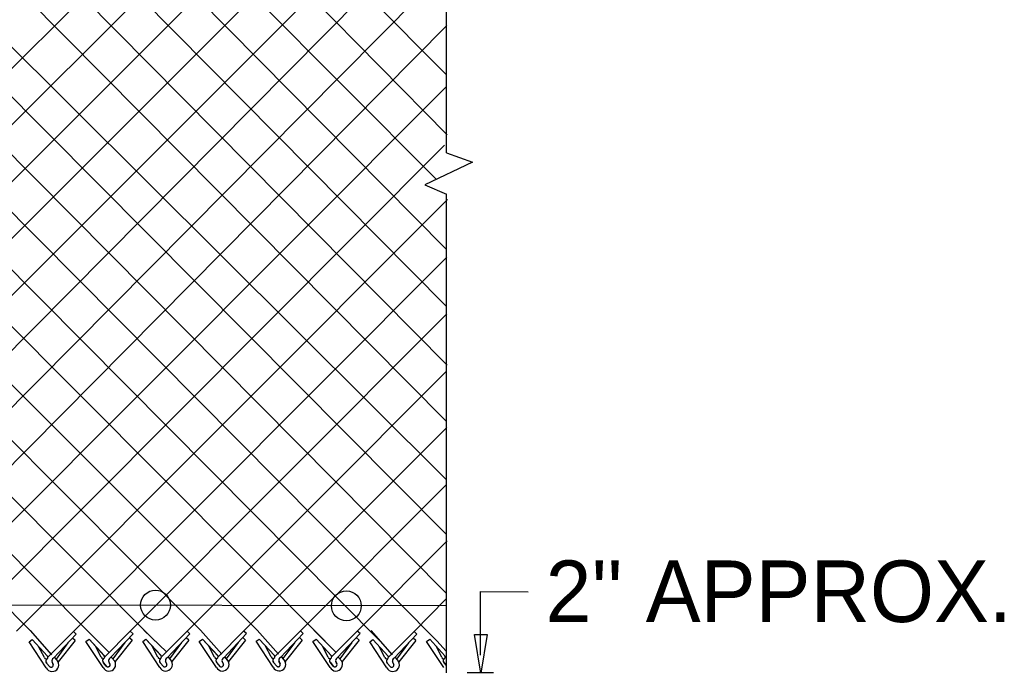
# Model space of a CAD drawing. Extents: x 0 to 2.85, y -0.1 to 1.83.
# Drawn here: x 1.173 to 1.3329, y 0.432 to 0.5382 of the extents above; entities that cross this region are included whole.
import ezdxf

# ---------------------------------------------------------------- set-up
doc = ezdxf.new("R2010")
doc.units = 0
for name, color, linetype in [('CT_Dimensions', 7, 'Continuous'), ('sb_Chainlink Fence', 7, 'Continuous'), ('sb_Existing Structural Steel', 7, 'Continuous')]:
    doc.layers.add(name, color=color, linetype=linetype)

msp = doc.modelspace()

# ---------------------------------------------------------------- linework, layer by layer
at = {"layer": 'CT_Dimensions'}
for p, q in [((1.2478234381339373, 0.4349259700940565), (1.2478234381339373, 0.4452738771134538)), ((1.2478234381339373, 0.4452738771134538), (1.2555261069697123, 0.44522173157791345)), ((1.245626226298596, 0.4321089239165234), (1.2499291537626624, 0.4321089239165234))]:
    msp.add_line(p, q, dxfattribs=at)
msp.add_lwpolyline([(1.248904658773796, 0.4382930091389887), (1.2478558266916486, 0.4320000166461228), (1.246806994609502, 0.4382930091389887)], close=True, dxfattribs=at)
at = {"layer": 'sb_Chainlink Fence'}
for p, q in [((1.2422905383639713, 0.5165766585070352), (1.2423058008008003, 0.5742715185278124)), ((1.1399018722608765, 0.5653949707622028), (1.242205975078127, 0.46352117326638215)), ((1.1170663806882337, 0.4387057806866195), (1.2423146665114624, 0.5641446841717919)), ((1.0856296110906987, 0.4444539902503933), (1.2030117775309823, 0.5615672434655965)), ((1.0889412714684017, 0.43860628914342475), (1.212232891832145, 0.5616340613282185)), ((1.098624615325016, 0.4387014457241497), (1.2214630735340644, 0.5617501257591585)), ((1.099199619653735, 0.5612496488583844), (1.2225566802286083, 0.4372006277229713)), ((1.1078450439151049, 0.4387247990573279), (1.2306873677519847, 0.5617466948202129)), ((1.1084207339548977, 0.5613164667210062), (1.231717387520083, 0.43698579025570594)), ((1.117650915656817, 0.5614325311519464), (1.2409415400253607, 0.43703703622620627)), ((1.1268752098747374, 0.5614291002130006), (1.242247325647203, 0.44502808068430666)), ((1.136094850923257, 0.5614703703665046), (1.2422290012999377, 0.45464034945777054)), ((1.1545640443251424, 0.561488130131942), (1.242202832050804, 0.4729775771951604)), ((1.1637851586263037, 0.5615549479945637), (1.2423944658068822, 0.4820903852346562)), ((1.1730153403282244, 0.5616710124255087), (1.2421925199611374, 0.49170328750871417)), ((1.1822396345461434, 0.5616675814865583), (1.2421467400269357, 0.5009699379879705)), ((1.1914592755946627, 0.5617088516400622), (1.2405411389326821, 0.5123525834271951)), ((1.200824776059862, 0.5617246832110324), (1.2424112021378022, 0.5194915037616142)), ((1.2100452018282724, 0.5617491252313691), (1.2422192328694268, 0.5293245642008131)), ((1.0895020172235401, 0.5610705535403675), (1.211527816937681, 0.43902946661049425)), ((1.0860534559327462, 0.5558884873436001), (1.20230738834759, 0.43900611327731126)), ((1.1262970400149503, 0.4386375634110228), (1.2423211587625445, 0.5558689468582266)), ((1.0860241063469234, 0.5466251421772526), (1.1949525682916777, 0.43724268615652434)), ((1.135521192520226, 0.4386888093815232), (1.242193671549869, 0.5464454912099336)), ((1.0853121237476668, 0.5380208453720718), (1.1838951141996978, 0.43899347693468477)), ((1.144345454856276, 0.4382857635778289), (1.2423139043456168, 0.5372986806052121)), ((1.0857454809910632, 0.5282548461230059), (1.1746709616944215, 0.43894223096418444)), ((1.154032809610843, 0.4388606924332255), (1.2422356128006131, 0.5273176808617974)), ((1.1632532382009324, 0.4388840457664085), (1.2419733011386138, 0.5178120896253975)), ((1.2422905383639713, 0.5165766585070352), (1.2465113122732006, 0.515088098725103)), ((1.2465113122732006, 0.515088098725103), (1.2387711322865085, 0.5114119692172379)), ((1.2387711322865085, 0.5114119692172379), (1.242288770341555, 0.509893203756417)), ((1.17247457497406, 0.4388650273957), (1.2424292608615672, 0.5090285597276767)), ((1.2422681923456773, 0.43210453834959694), (1.242288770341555, 0.509893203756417)), ((1.1817052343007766, 0.4387968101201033), (1.2423555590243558, 0.4996556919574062)), ((1.1909293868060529, 0.438848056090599), (1.2423543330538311, 0.49043740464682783)), ((1.2001491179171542, 0.43885457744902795), (1.242157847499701, 0.48101512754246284)), ((1.2093416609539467, 0.4388606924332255), (1.242357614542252, 0.4719717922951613)), ((1.218562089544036, 0.4388840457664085), (1.242224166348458, 0.4626086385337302)), ((1.2277834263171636, 0.4388650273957), (1.2424068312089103, 0.45351950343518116)), ((1.199139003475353, 0.44703465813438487), (1.1992236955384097, 0.4471193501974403)), ((1.0856561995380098, 0.44326039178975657), (1.2423033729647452, 0.4430188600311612)), ((1.1746709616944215, 0.43894223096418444), (1.1781461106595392, 0.43502934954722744)), ((1.1775522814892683, 0.43462621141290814), (1.1817052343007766, 0.4387968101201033)), ((1.178465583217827, 0.4344630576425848), (1.1821583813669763, 0.43838618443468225)), ((1.1821583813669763, 0.43838618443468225), (1.1817052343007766, 0.4387968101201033)), ((1.1838951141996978, 0.43899347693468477), (1.1874928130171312, 0.43540281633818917)), ((1.1867764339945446, 0.43467745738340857), (1.1909293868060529, 0.438848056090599)), ((1.1876897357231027, 0.4345143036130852), (1.1913825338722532, 0.43843743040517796)), ((1.1913825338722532, 0.43843743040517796), (1.1909293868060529, 0.438848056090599)), ((1.1931148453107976, 0.438999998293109), (1.196790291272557, 0.43548537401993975)), ((1.1959961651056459, 0.4346839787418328), (1.2001491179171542, 0.43885457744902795)), ((1.1969094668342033, 0.43452082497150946), (1.2006022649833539, 0.43844395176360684)), ((1.2006022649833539, 0.43844395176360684), (1.2001491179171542, 0.43885457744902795)), ((1.20230738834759, 0.43900611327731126), (1.2057825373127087, 0.4350932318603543)), ((1.2051887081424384, 0.4346900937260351), (1.2093416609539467, 0.4388606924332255)), ((1.2061020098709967, 0.4345269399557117), (1.2097948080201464, 0.43845006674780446)), ((1.2097948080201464, 0.43845006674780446), (1.2093416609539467, 0.4388606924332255)), ((1.211527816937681, 0.43902946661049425), (1.2150029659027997, 0.43511658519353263)), ((1.2144091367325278, 0.43471344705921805), (1.218562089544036, 0.4388840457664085)), ((1.2153224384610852, 0.43455029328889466), (1.2190152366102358, 0.43847342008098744)), ((1.2190152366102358, 0.43847342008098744), (1.218562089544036, 0.4388840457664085)), ((1.2207491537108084, 0.43901044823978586), (1.2243642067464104, 0.43539080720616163)), ((1.2236304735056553, 0.4346944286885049), (1.2277834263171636, 0.4388650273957)), ((1.224543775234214, 0.43453127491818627), (1.228236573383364, 0.438454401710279)), ((1.228236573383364, 0.438454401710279), (1.2277834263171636, 0.4388650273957)), ((1.2299798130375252, 0.43894223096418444), (1.2334549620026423, 0.43502934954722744)), ((1.232861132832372, 0.43462621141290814), (1.2370140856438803, 0.4387968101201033)), ((1.233774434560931, 0.4344630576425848), (1.23746723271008, 0.43838618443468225)), ((1.23746723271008, 0.43838618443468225), (1.2370140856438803, 0.4387968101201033)), ((1.1745060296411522, 0.43712460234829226), (1.175016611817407, 0.4374734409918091)), ((1.1772955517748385, 0.4329011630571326), (1.1745060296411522, 0.43712460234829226)), ((1.175016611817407, 0.4374734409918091), (1.1774850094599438, 0.43481311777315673)), ((1.175016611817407, 0.4374734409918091), (1.1775008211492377, 0.4347973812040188)), ((1.1808150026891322, 0.43694584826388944), (1.178872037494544, 0.43430117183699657)), ((1.1820045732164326, 0.4373260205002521), (1.1792421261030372, 0.4338515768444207)), ((1.1820045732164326, 0.4373260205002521), (1.181551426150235, 0.43773664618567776)), ((1.1837301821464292, 0.4371758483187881), (1.1842407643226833, 0.43752468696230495)), ((1.1865197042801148, 0.4329524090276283), (1.1837301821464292, 0.4371758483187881)), ((1.1842407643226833, 0.43752468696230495), (1.1867091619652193, 0.4348643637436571)), ((1.1842407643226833, 0.43752468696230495), (1.186724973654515, 0.4348486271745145)), ((1.1900391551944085, 0.43699709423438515), (1.1880961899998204, 0.43435241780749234)), ((1.191228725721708, 0.4373772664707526), (1.1884662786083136, 0.4339028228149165)), ((1.191228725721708, 0.4373772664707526), (1.1907755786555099, 0.4377878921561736)), ((1.1929499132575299, 0.4371823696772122), (1.1934604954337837, 0.43753120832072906)), ((1.195739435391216, 0.4329589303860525), (1.1929499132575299, 0.4371823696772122)), ((1.1934604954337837, 0.43753120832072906), (1.1959288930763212, 0.4348708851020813)), ((1.1934604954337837, 0.43753120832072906), (1.1959447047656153, 0.4348551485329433)), ((1.1992588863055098, 0.4370036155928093), (1.1973159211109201, 0.43435893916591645)), ((1.2004484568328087, 0.43738378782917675), (1.1976860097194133, 0.43390934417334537)), ((1.2004484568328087, 0.43738378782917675), (1.1999953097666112, 0.4377944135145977)), ((1.2021424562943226, 0.43718848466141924), (1.2026530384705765, 0.43753732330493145)), ((1.204931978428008, 0.4329650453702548), (1.2021424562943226, 0.43718848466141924)), ((1.2026530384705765, 0.43753732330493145), (1.205121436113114, 0.43487700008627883)), ((1.2026530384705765, 0.43753732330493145), (1.205137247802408, 0.4348612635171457)), ((1.2084514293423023, 0.43700973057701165), (1.2065084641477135, 0.43436505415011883)), ((1.2096409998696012, 0.4373899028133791), (1.2068785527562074, 0.433915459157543)), ((1.2096409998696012, 0.4373899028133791), (1.2091878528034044, 0.4378005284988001)), ((1.211362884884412, 0.43721183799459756), (1.2118734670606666, 0.43756067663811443)), ((1.214152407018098, 0.4329883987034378), (1.211362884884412, 0.43721183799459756)), ((1.2118734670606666, 0.43756067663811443), (1.2143418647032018, 0.4349003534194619)), ((1.2118734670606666, 0.43756067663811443), (1.2143576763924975, 0.4348846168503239)), ((1.2176718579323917, 0.4370330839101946), (1.2157288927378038, 0.4343884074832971)), ((1.2188614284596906, 0.437413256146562), (1.2160989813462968, 0.43393881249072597)), ((1.2188614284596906, 0.437413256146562), (1.218408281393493, 0.43782388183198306)), ((1.2205842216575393, 0.437192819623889), (1.2210948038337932, 0.4375416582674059)), ((1.2233737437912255, 0.4329693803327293), (1.2205842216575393, 0.437192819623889)), ((1.2210948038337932, 0.4375416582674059), (1.2235632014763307, 0.4348813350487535)), ((1.2210948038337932, 0.4375416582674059), (1.2235790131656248, 0.4348655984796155)), ((1.2268931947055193, 0.43701406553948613), (1.2249502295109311, 0.43436938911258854)), ((1.2280827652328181, 0.43739423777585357), (1.2253203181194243, 0.4339197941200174)), ((1.2280827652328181, 0.43739423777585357), (1.227629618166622, 0.4378048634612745)), ((1.229814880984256, 0.43712460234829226), (1.2303254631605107, 0.4374734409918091)), ((1.2326044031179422, 0.4329011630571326), (1.229814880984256, 0.43712460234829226)), ((1.2303254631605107, 0.4374734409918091), (1.2327938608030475, 0.43481311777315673)), ((1.2303254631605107, 0.4374734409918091), (1.2328096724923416, 0.4347973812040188)), ((1.236123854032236, 0.43694584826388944), (1.2341808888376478, 0.43430117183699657)), ((1.2373134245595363, 0.4373260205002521), (1.234550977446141, 0.4338515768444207)), ((1.2373134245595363, 0.4373260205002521), (1.236860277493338, 0.43773664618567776)), ((1.2390390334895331, 0.4371758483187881), (1.239549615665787, 0.43752468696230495)), ((1.2418285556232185, 0.4329524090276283), (1.2390390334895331, 0.4371758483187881)), ((1.239549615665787, 0.43752468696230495), (1.242018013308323, 0.4348643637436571)), ((1.239549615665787, 0.43752468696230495), (1.2420338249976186, 0.4348486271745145)), ((1.2407177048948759, 0.43728906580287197), (1.24223882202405, 0.4355763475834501)), ((1.1769779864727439, 0.43456755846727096), (1.1760487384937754, 0.4363439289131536)), ((1.1862021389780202, 0.43461880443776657), (1.1852728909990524, 0.4363951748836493)), ((1.19542187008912, 0.4346253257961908), (1.1944926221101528, 0.43640169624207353)), ((1.204614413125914, 0.4346314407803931), (1.2036851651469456, 0.4364078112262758)), ((1.2138348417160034, 0.43465479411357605), (1.212905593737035, 0.4364311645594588)), ((1.223056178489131, 0.4346357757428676), (1.2221269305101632, 0.43641214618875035)), ((1.2322868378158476, 0.43456755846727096), (1.2313575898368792, 0.4363439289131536)), ((1.2415109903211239, 0.43461880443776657), (1.2405817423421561, 0.4363951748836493)), ((1.1778126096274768, 0.4331129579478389), (1.177350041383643, 0.43366683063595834)), ((1.177350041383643, 0.43366683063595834), (1.17785966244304, 0.43306338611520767)), ((1.1784103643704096, 0.4334398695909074), (1.1782231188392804, 0.43384551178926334)), ((1.1782238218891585, 0.4338311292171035), (1.1784099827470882, 0.43344906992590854)), ((1.1786202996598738, 0.4345724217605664), (1.1791872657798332, 0.4339012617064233)), ((1.1786278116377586, 0.4345621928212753), (1.1791901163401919, 0.4338989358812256)), ((1.1791872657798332, 0.4339012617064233), (1.1792289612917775, 0.43382332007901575)), ((1.1792289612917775, 0.43382332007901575), (1.1792644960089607, 0.43373992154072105)), ((1.1870367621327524, 0.43316420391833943), (1.1865741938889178, 0.43371807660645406)), ((1.1865741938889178, 0.43371807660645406), (1.1870838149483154, 0.433114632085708)), ((1.1876345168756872, 0.4334911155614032), (1.1874472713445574, 0.43389675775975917)), ((1.1874479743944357, 0.4338823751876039), (1.1876341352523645, 0.43350031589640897)), ((1.1878444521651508, 0.4346236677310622), (1.1884114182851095, 0.433952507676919)), ((1.187851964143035, 0.43461343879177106), (1.188414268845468, 0.4339501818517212)), ((1.1884114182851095, 0.433952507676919), (1.1884531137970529, 0.43387456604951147)), ((1.1884531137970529, 0.43387456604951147), (1.1884886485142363, 0.4337911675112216)), ((1.1962564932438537, 0.43317072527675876), (1.1957939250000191, 0.43372459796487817)), ((1.1957939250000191, 0.43372459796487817), (1.196303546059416, 0.43312115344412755)), ((1.1968542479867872, 0.4334976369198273), (1.1966670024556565, 0.433903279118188)), ((1.1966677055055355, 0.433888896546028), (1.1968538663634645, 0.4335068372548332)), ((1.1970641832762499, 0.4346301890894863), (1.1976311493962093, 0.4339590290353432)), ((1.1970716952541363, 0.43461996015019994), (1.1976339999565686, 0.43395670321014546)), ((1.1976311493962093, 0.4339590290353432), (1.1976728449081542, 0.43388108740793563)), ((1.1976728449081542, 0.43388108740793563), (1.197708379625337, 0.433797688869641)), ((1.205449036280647, 0.4331768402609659), (1.2049864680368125, 0.43373071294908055)), ((1.2049864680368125, 0.43373071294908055), (1.2054960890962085, 0.4331272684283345)), ((1.2060467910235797, 0.4335037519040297), (1.2058595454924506, 0.4339093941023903)), ((1.205860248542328, 0.4338950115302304), (1.206046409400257, 0.43351295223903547)), ((1.206256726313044, 0.4346363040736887), (1.2068236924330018, 0.4339651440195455)), ((1.2062642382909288, 0.4346260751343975), (1.2068265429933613, 0.4339628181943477)), ((1.2068236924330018, 0.4339651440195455), (1.2068653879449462, 0.43388720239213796)), ((1.2068653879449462, 0.43388720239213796), (1.2069009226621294, 0.4338038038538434)), ((1.2146694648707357, 0.43320019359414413), (1.2142068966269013, 0.43375406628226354)), ((1.2142068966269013, 0.43375406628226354), (1.214716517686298, 0.4331506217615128)), ((1.2152672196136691, 0.43352710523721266), (1.21507997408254, 0.43393274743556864)), ((1.215080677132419, 0.4339183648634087), (1.215266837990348, 0.43353630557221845)), ((1.2154771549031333, 0.4346596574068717), (1.2160441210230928, 0.4339884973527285)), ((1.2154846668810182, 0.4346494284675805), (1.2160469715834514, 0.43398617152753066)), ((1.2160441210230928, 0.4339884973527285), (1.2160858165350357, 0.43391055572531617)), ((1.2160858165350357, 0.43391055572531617), (1.2161213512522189, 0.43382715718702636)), ((1.2238908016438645, 0.4331811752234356), (1.2234282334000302, 0.433735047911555)), ((1.2234282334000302, 0.433735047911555), (1.2239378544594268, 0.43313160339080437)), ((1.2244885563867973, 0.4335080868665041), (1.2243013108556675, 0.4339137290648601)), ((1.2243020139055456, 0.43389934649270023), (1.2244881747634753, 0.43351728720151)), ((1.2246984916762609, 0.4346406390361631), (1.2252654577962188, 0.43396947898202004)), ((1.2247060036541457, 0.434630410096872), (1.225268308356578, 0.43396715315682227)), ((1.2252654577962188, 0.43396947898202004), (1.2253071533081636, 0.43389153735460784)), ((1.2253071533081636, 0.43389153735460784), (1.225342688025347, 0.4338081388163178)), ((1.2331214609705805, 0.4331129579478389), (1.2326588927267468, 0.43366683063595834)), ((1.2326588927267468, 0.43366683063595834), (1.2331685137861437, 0.43306338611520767)), ((1.2337192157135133, 0.4334398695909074), (1.2335319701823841, 0.43384551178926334)), ((1.2335326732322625, 0.4338311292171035), (1.233718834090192, 0.43344906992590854)), ((1.2339291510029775, 0.4345724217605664), (1.234496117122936, 0.4339012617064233)), ((1.2339366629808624, 0.4345621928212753), (1.2344989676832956, 0.4338989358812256)), ((1.234496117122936, 0.4339012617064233), (1.2345378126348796, 0.43382332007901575)), ((1.2345378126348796, 0.43382332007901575), (1.2345733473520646, 0.43373992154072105)), ((1.2422687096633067, 0.4332562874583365), (1.2418830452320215, 0.43371807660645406)), ((1.2418830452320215, 0.43371807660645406), (1.24222681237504, 0.4333110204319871))]:
    msp.add_line(p, q, dxfattribs=at)
for centre in [(1.1950301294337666, 0.4430882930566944), (1.2260178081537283, 0.44296607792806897)]:
    msp.add_circle(centre, 0.0024276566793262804, dxfattribs=at)
for centre, radius, start, end in [((1.1772664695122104, 0.43461806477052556), 0.0002928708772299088, 189.9304409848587, 40.97853800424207), ((1.1776470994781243, 0.4339911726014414), 0.000440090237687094, 126.9947472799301, 219.79833989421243), ((1.1776591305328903, 0.4339906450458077), 0.0004476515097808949, 127.7656421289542, 226.33281459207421), ((1.178255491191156, 0.43337601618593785), 0.001070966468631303, 206.32021657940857, 29.22686940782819), ((1.1780791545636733, 0.43333553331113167), 0.0003472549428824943, 219.86319118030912, 17.48524419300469), ((1.1780804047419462, 0.4333338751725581), 0.00034912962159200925, 230.78260140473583, 19.265642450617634), ((1.178667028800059, 0.4340279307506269), 0.000479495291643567, 114.84216649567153, 203.51671506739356), ((1.1864906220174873, 0.4346693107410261), 0.0002928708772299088, 189.9304409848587, 40.97853800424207), ((1.1868712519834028, 0.4340424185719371), 0.000440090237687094, 126.9947472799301, 219.79833989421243), ((1.1868832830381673, 0.43404189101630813), 0.0004476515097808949, 127.7656421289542, 226.33281459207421), ((1.1874796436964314, 0.43342726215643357), 0.001070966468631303, 206.32021657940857, 29.22686940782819), ((1.187303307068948, 0.4333867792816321), 0.0003472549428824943, 219.86319118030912, 17.48524419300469), ((1.1873045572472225, 0.4333851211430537), 0.00034912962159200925, 230.78260140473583, 19.265642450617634), ((1.1878911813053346, 0.4340791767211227), 0.000479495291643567, 114.84216649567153, 203.51671506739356), ((1.195710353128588, 0.4346758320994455), 0.0002928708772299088, 189.9304409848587, 40.97853800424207), ((1.196090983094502, 0.43404893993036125), 0.000440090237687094, 126.9947472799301, 219.79833989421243), ((1.1961030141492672, 0.4340484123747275), 0.0004476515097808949, 127.7656421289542, 226.33281459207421), ((1.196699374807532, 0.4334337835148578), 0.001070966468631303, 206.32021657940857, 29.22686940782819), ((1.196523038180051, 0.4333933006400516), 0.0003472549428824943, 219.86319118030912, 17.48524419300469), ((1.1965242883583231, 0.433391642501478), 0.00034912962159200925, 230.78260140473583, 19.265642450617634), ((1.1971109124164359, 0.4340856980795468), 0.000479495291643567, 114.84216649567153, 203.51671506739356), ((1.2049028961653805, 0.4346819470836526), 0.0002928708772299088, 189.9304409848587, 40.97853800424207), ((1.2052835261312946, 0.4340550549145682), 0.000440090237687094, 126.9947472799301, 219.79833989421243), ((1.205295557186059, 0.4340545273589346), 0.0004476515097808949, 127.7656421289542, 226.33281459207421), ((1.2058919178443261, 0.43343989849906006), 0.001070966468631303, 206.32021657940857, 29.22686940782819), ((1.2057155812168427, 0.4333994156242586), 0.0003472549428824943, 219.86319118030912, 17.48524419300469), ((1.2057168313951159, 0.4333977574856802), 0.00034912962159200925, 230.78260140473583, 19.265642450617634), ((1.2063034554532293, 0.4340918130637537), 0.000479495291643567, 114.84216649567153, 203.51671506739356), ((1.21412332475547, 0.4347053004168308), 0.0002928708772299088, 189.9304409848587, 40.97853800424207), ((1.214503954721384, 0.4340784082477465), 0.000440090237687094, 126.9947472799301, 219.79833989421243), ((1.2145159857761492, 0.4340778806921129), 0.0004476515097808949, 127.7656421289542, 226.33281459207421), ((1.215112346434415, 0.43346325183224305), 0.001070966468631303, 206.32021657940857, 29.22686940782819), ((1.2149360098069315, 0.43342276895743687), 0.0003472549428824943, 219.86319118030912, 17.48524419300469), ((1.214937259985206, 0.4334211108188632), 0.00034912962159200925, 230.78260140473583, 19.265642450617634), ((1.2155238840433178, 0.43411516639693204), 0.000479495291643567, 114.84216649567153, 203.51671506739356), ((1.2233446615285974, 0.4346862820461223), 0.0002928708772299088, 189.9304409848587, 40.97853800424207), ((1.223725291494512, 0.43405938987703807), 0.000440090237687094, 126.9947472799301, 219.79833989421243), ((1.2237373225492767, 0.43405886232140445), 0.0004476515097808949, 127.7656421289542, 226.33281459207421), ((1.2243336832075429, 0.4334442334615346), 0.001070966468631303, 206.32021657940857, 29.22686940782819), ((1.2241573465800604, 0.4334037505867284), 0.0003472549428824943, 219.86319118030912, 17.48524419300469), ((1.2241585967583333, 0.4334020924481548), 0.00034912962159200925, 230.78260140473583, 19.265642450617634), ((1.224745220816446, 0.4340961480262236), 0.000479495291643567, 114.84216649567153, 203.51671506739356), ((1.232575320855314, 0.43461806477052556), 0.0002928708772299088, 189.9304409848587, 40.97853800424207), ((1.232955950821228, 0.4339911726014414), 0.000440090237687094, 126.9947472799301, 219.79833989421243), ((1.2329679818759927, 0.4339906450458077), 0.0004476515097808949, 127.7656421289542, 226.33281459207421), ((1.2335643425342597, 0.43337601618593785), 0.001070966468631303, 206.32021657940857, 29.22686940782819), ((1.233388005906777, 0.43333553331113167), 0.0003472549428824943, 219.86319118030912, 17.48524419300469), ((1.2333892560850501, 0.4333338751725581), 0.00034912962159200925, 230.78260140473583, 19.265642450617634), ((1.2339758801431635, 0.4340279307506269), 0.000479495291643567, 114.84216649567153, 203.51671506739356), ((1.241799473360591, 0.4346693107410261), 0.0002928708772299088, 189.9304409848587, 40.97853800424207), ((1.2421801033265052, 0.4340424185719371), 0.000440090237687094, 126.9947472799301, 219.79833989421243), ((1.2421921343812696, 0.43404189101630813), 0.0004476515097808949, 127.7656421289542, 226.33281459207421)]:
    msp.add_arc(centre, radius, start, end, dxfattribs=at)
at = {"layer": 'sb_Existing Structural Steel'}
msp.add_line((1.2370140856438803, 0.4387968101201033), (1.242168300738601, 0.4440484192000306), dxfattribs=at)

# ---------------------------------------------------------------- texts
at = {"layer": 'CT_Dimensions'}
msp.add_text("2'' APPROX.", height=0.01, dxfattribs=at).set_placement((1.2583742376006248, 0.44033575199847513))

doc.saveas('drawing.dxf')
